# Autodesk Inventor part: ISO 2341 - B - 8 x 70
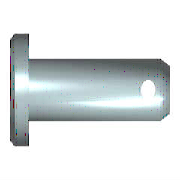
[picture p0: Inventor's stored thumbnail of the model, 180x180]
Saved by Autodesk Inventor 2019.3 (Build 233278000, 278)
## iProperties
Created: 2018-01
Part Number: ISO 2341 - B - 8 x 70
Material: Ocel
Description: Čepy závěsu s hlavou
Document SubType Name: Modeling
Standard: ISO 2341
Designer: B-hon
Standards Organization: BSI
Language: cs-CZ
Size Designation: B - 8 x 70
Categories: <MemberInstance><Categories><Category DisplayName="Spojovací materiál" InternalName="e4da775c-781d-43d5-af7c-5136215cf5a6" Mnemonic="FSTN"><Category DisplayName
Density: 7.85 g/cm^3
Appearance: Plech
IsCustomPart: 0
Author: B-hon
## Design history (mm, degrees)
sketch "Náčrt1"
  geometry: L1 (-3, 0)-(-3, 7); L2 (-3, 7)-(0, 7); L3 (0, 7)-(0, 4); L4 (0, 4)-(70, 4); L5 (70, 4)-(70, 0); L6 (-3, 0)-(70, 0); L7 (-4, 0)-(17, 0) reference; L8 (0, -0.98)-(0, 3.08) reference; C1 r 1 at (66.5, 0)
  constraints: 12 end point, 3 parallel, 2 collinear, 2 perpendicular, 1 centre point, 1 point on line, 1 vertical
  dimensions: "d0" = 8 diameter of L4 L6 (= NND); "d1" = 14 diameter of L2 L6 (= KOD); "d2" = 3 distance of L1.end L2.end (= KOH); "d3" = 70 distance of L3.end L4.end (= NLG); "d5" = 3.5 distance from line of L5 C1.centre (= DIST); "d6" = 2 diameter of C1 (= BOR)
revolve "Těleso" stored, may be unused: angle "d4" = 90 deg
extrude "Otvor" cut sketch "Náčrt1" extent not by distance; stored distance "d7" = 8 (= NND); taper "d8" = 0 deg
workaxis "Work Axis1"
workplane "Work Plane1"
body "Solid1"
chamfer "Zkosení1" distance "d9" = 1 (= PHH2); stored, may be unused: angle "d10" = 45 deg (= FAWI2), second distance "d16" = 1 (= PHH2)
chamfer "Zkosení2" distance "d11" = 2 (= PHH1); stored, may be unused: angle "d12" = 30 deg (= FAWI1), second distance "d17" = 2 (= PHH1)
other parameters: "PHH1" = 2 [user parameter; used in 2 equation terms], "PHH2" = 1 [user parameter; used in 2 equation terms], "KOD" = 14 [user parameter; used in 1 equation term], "KOH" = 3 [user parameter; used in 1 equation term], "NND" = 8 [user parameter; used in 2 equation terms], "FAWI1" = 30 deg [user parameter; used in 1 equation term], "FAWI2" = 45 deg [user parameter; used in 1 equation term], "DIST" = 3.5 [user parameter; used in 1 equation term], "BOR" = 2 [user parameter; used in 1 equation term], "NLG" = 70 [user parameter; used in 1 equation term], "d13" = 0, "d14" = 0, "d27" = 0, "d28" = 0, "d29" = 0, "d30" = 0, "d31" = 0
